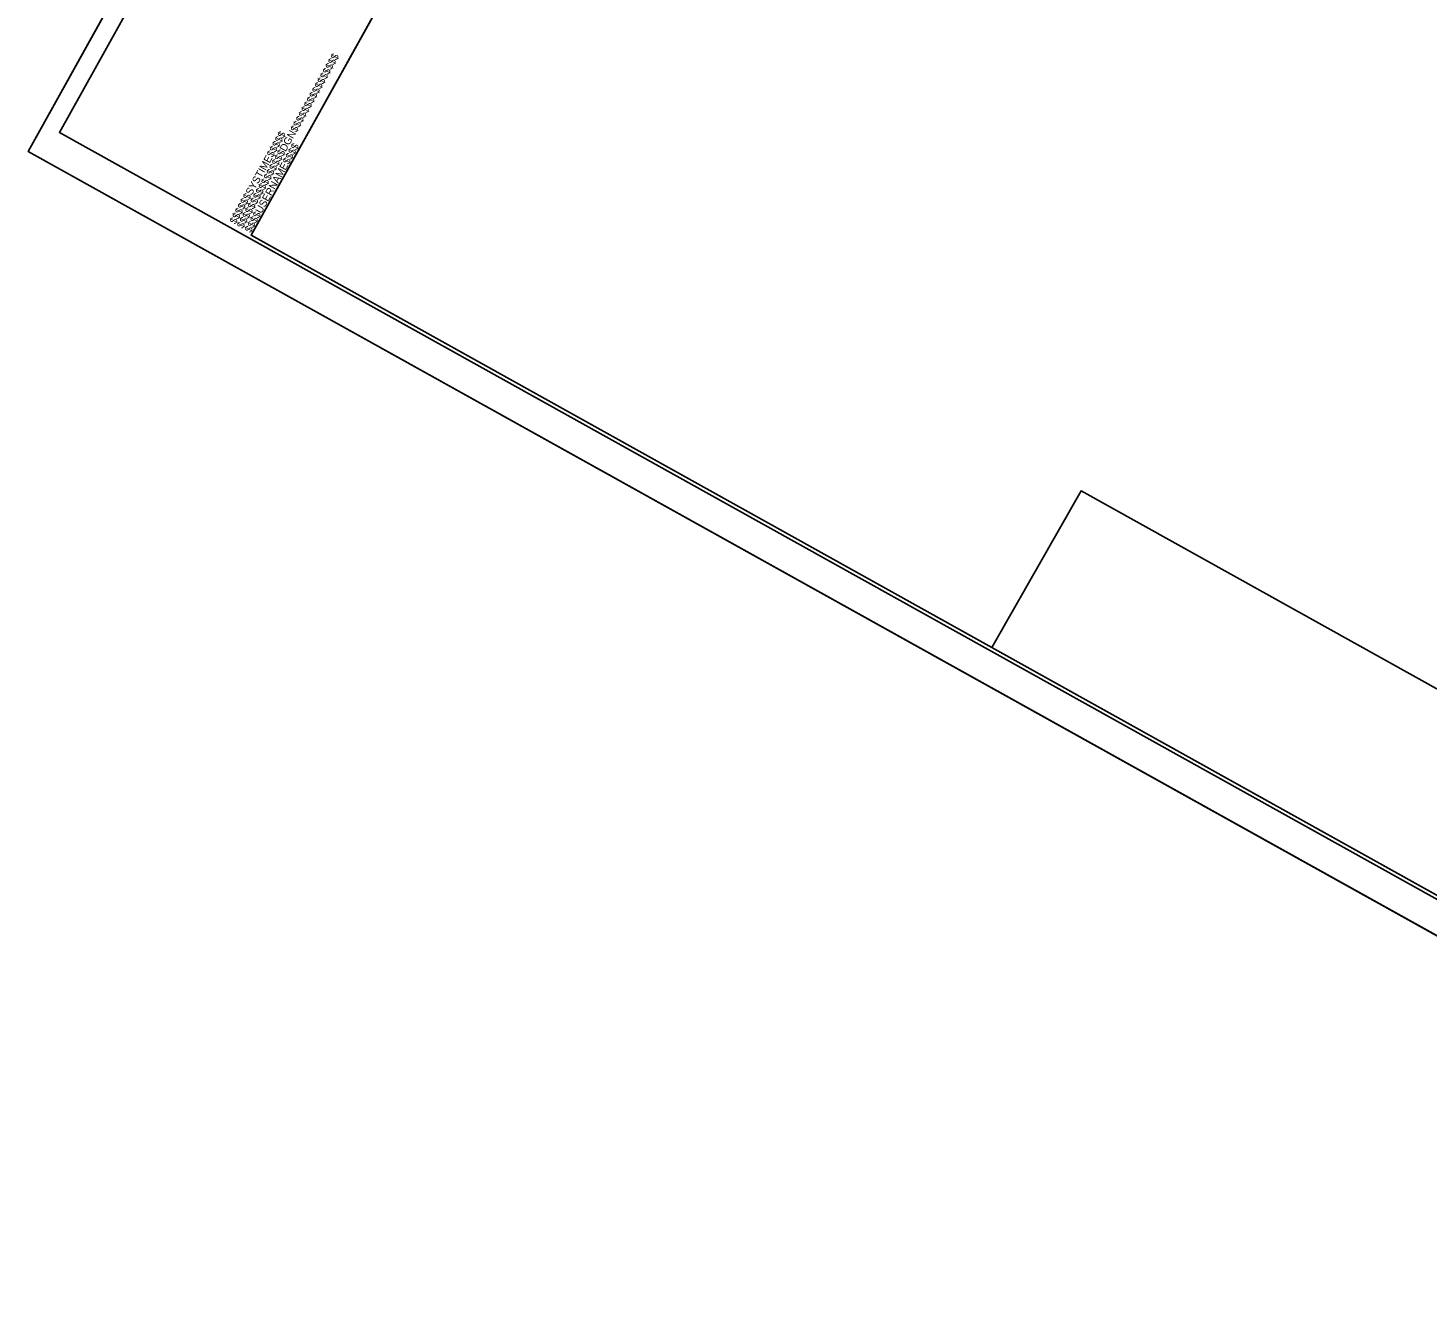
# Model space of a CAD drawing. Extents: x 1763454 to 1765483, y 710212 to 712009.
# Drawn here: x 1763476 to 1764468, y 710212 to 711119 of the extents above; entities that cross this region are included whole.
import ezdxf

# ---------------------------------------------------------------- set-up
doc = ezdxf.new("R2010")
doc.units = 0
for name, color, linetype in [('Default', 7, 'Continuous'), ('Sheet Border Standard 30in CELL', 7, 'Continuous'), ('Sheet Cutting Line CELL', 7, 'Continuous'), ('Sheet Layout Plan Border', 7, 'Continuous'), ('Sheet Plot Border Inside CELL', 7, 'Continuous'), ('Sheet Plot Border Outside CELL', 7, 'Continuous')]:
    doc.layers.add(name, color=color, linetype=linetype)

msp = doc.modelspace()

# ---------------------------------------------------------------- linework, layer by layer
at = {"layer": 'Default'}
msp.add_lwpolyline([(1763634.19, 710972.32), (1763634.19, 710972.32), (1763806.94, 711282.53), (1764422.61, 711735.08), (1765280.77, 711257.19), (1765145.7, 711014.65), (1765228.38, 710968.6), (1764852.61, 710293.81)], close=True, dxfattribs=at)
at = {"layer": 'Sheet Border Standard 30in CELL'}
msp.add_lwpolyline([(1765455.55, 711159.88), (1764145.05, 711889.67), (1763634.19, 710972.32), (1764944.69, 710242.53)], close=True, dxfattribs=at)
at = {"layer": 'Sheet Cutting Line CELL'}
for p, q in [((1764011.31, 711992.76), (1763476.13, 711031.72)), ((1763476.13, 711031.72), (1764947.38, 710212.42))]:
    msp.add_line(p, q, dxfattribs=at)
at = {"layer": 'Sheet Layout Plan Border'}
msp.add_line((1763634.19, 710972.32), (1763865.66, 711387.96), dxfattribs=at)
msp.add_lwpolyline([(1764852.55, 710293.84), (1764570.56, 710450.87), (1764630.41, 710563.94), (1764222.54, 710791), (1764159.35, 710679.87), (1763634.19, 710972.32)], dxfattribs=at)
at = {"layer": 'Sheet Plot Border Inside CELL'}
msp.add_lwpolyline([(1765467.71, 711156.02), (1764011.74, 711966.82), (1763498.41, 711045.01), (1764954.37, 710234.22)], close=True, dxfattribs=at)
at = {"layer": 'Sheet Plot Border Outside CELL'}
msp.add_lwpolyline([(1765482.56, 711173.45), (1764011.31, 711992.76), (1763476.13, 711031.72), (1764947.38, 710212.42)], close=True, dxfattribs=at)

# ---------------------------------------------------------------- texts
at = {"layer": 'Sheet Border Standard 30in CELL'}
for s, p in [('$$$$$$$$$$$$$$$$DGN$$$$$$$$$$$$$$$$', (1763628.36, 710976.54)), ('$$$$$$SYSTIME$$$$$', (1763623.17, 710979.66)), ('$$$$USERNAME$$$$', (1763633.91, 710973.56))]:
    msp.add_text(s, height=5.25, rotation=60.88754, dxfattribs=at).set_placement(p)

doc.saveas('drawing.dxf')
